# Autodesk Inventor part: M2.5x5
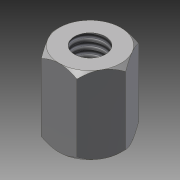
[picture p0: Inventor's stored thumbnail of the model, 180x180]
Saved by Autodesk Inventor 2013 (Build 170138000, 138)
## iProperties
Created: 2012-08
Part Number: M2.5x5
Material: Stahl
Document SubType Name: Modeling
Designer: rYan
Density: 7.85 g/cm^3
Mass: 3.36246 g
Surface Area: 5.74911 cm^2
Volume: 0.428339 cm^3
Author: rYan
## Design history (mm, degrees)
sketch "Skizze1"
  geometry: L1 (2.309, 0)-(1.155, -2); L2 (1.155, -2)-(-1.155, -2); L3 (-1.155, -2)-(-2.309, 0); L4 (-2.309, 0)-(-1.155, 2); L5 (-1.155, 2)-(1.155, 2); L6 (1.155, 2)-(2.309, 0); 2 further points
  constraints: 12 end point, 1 coincident, 13 other
  dimensions: "SW" = 4 distance between parallel lines of L2 L5
extrude "Extrusion1" new body sketch "Skizze1" taper "d2" = 0 deg; stored distance "L" = 5
sketch "Skizze2"
  geometry: 2 further points
  constraints: 1 coincident
hole "Bohrung1" sketch "Skizze2" at (0, 0) diameter "d3" = 2.013; stored, may be unused: countersink angle "d7" = 90 deg, drill point angle "d9" = 118 deg; dims "d4" = 6, "d5" = 4, "d6" = 2, "d8" = 8
sketch "Innenradius"
  geometry: L1 (2.309, 0)-(1.155, 2) reference; C1 r 2 at (0, 0); 1 further point
  constraints: 1 centre point, 1 coincident, 1 tangent
sketch "Skizze7"
  geometry: L1 (-1.006, 2.5)-(1.006, 2.5) reference; L2 (-1.155, 2.5)-(-2.309, 2.5) reference; L3 (-2.309, 2.5)-(-1.155, 2.5) reference; L4 (-1.155, 2.5)-(1.155, 2.5) reference; L5 (1.155, 2.5)-(2.309, 2.5) reference; L6 (2.309, 2.5)-(1.155, 2.5) reference; L7 (1.155, 2.5)-(-1.155, 2.5) reference; L8 (1.006, -2.5)-(-1.006, -2.5) reference; L9 (-2.309, -2.5)-(-1.155, -2.5) reference; L10 (-1.155, -2.5)-(1.155, -2.5) reference; L11 (1.155, -2.5)-(2.309, -2.5) reference; L12 (2.309, -2.5)-(1.155, -2.5) reference; L13 (1.155, -2.5)-(-1.155, -2.5) reference; L14 (-1.155, -2.5)-(-2.309, -2.5) reference; L15 (0, -14)-(0, 14) reference; L16 (0, 2.5)-(0, -2.5); L17 (2, 2.5)-(-2, 2.5) reference; L18 (2, 2.5)-(2.309, 2.5); L19 (2.309, 2.191)-(2, 2.5); L20 (2.309, 2.5)-(2.309, 2.191); 1 further point
  constraints: 8 end point, 2 midpoint, 2 point on line, 1 collinear, 1 perpendicular
  dimensions: "d16" = 45 deg angle of L5 L19
revolve "Umdrehung1" sketch "Skizze7" stored, may be unused: angle "d17" = 90 deg
mirror "Spiegeln1"
node "Volumenkörper1"
node "Projizierte Kontur5"
node "Projizierte Kontur6"
